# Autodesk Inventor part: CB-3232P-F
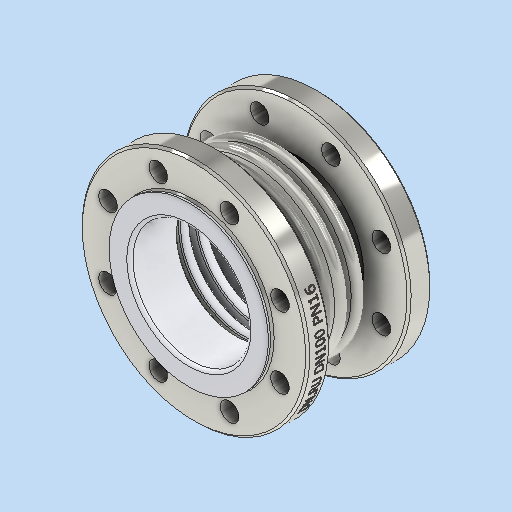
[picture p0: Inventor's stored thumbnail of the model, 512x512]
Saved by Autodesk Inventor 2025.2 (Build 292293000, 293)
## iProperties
Company: DN.RU
Created: 2026-04
Part Number: CB-3232P-F
Material: Типовые
Document SubType Name: Modeling
Designer: DN.RU
Density: 6.32462 g/cm^3
Appearance: По умолчанию
Description: D140-02141
Mass: 9000 g
Surface Area: 3707.62 cm^2
Volume: 1423.01 cm^3
Author: DN.RU
Title: Компенсатор сильфонный осевой DN.ru Ду100 Ру16
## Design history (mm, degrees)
sketch "Эскиз1"
  geometry: L1 (0, 0)-(0, -60); L2 (63, -60)-(63, 0); L3 (63, 0)-(0, 0); L4 (63, 0)-(63, 0); L5 (45, 0)-(81, 0); L6 (45, -5)-(81, -5); L7 (81, 5)-(45, 5); L8 (81, -3)-(45, -3); L9 (45, 3)-(81, 3); L10 (81, -11)-(45, -11); L11 (45, -13)-(81, -13); L12 (45, -16)-(81, -16); L13 (45, -21)-(81, -21); L14 (81, -19)-(45, -19); L15 (0, -60)-(63, -60); L16 (63, -60)-(57, -60); L17 (57, -60)-(57, -19); L18 (63, -13)-(61, -13); L19 (61, -13)-(61, -3); L20 (63, 3)-(62, 3); L21 (62, 3)-(61, 0); L22 (0, -60)-(0, -38); L23 (0, -38)-(110, -38); L24 (110, -38)-(110, -60); L25 (110, -60)-(0, -60); L26 (63, -38)-(63, -48); L27 (63, -48)-(66, -48); L28 (66, -48)-(66, -38); L29 (66, -38)-(63, -38); L30 (86, 0)-(63, 0); A1 r 5 centre (45, 0) between (45, 5) and (45, -5); A2 r 5 centre (81, 0) between (81, -5) and (81, 5); A3 r 3 centre (45, 0) between (45, 3) and (45, -3); A4 r 3 centre (81, 0) between (81, -3) and (81, 3); A5 r 3 centre (45, -16) between (45, -13) and (45, -19); A6 r 5 centre (45, -16) between (45, -11) and (45, -21); A7 r 3 centre (81, -16) between (81, -19) and (81, -13); A8 r 5 centre (81, -16) between (81, -21) and (81, -11); 18 further points
  constraints: 64 end point, 17 point on circle, 13 point on line, 8 centre point, 7 parallel, 4 perpendicular, 4 tangent, 3 midpoint, 2 vertical, 1 collinear, 1 horizontal, 25 other
  dimensions: "d0" = 60 distance of L1.start L1.end; "d3" = 0 distance of L2.end L4.end; "d4" = 18 distance of L4.end L5.end; "d5" = 10 diameter of A2; "d6" = 2 distance between parallel lines of L6 L8; "d9" = 16 distance of L4.end point (63, -16); "d18" = 2 distance of L18.start L18.end; "d19" = 1 distance of L20.start L20.end; "d27" = 57 distance between parallel lines of L1 L17; "d28" = 6 distance between parallel lines of L2 L17; "d29" = 22 distance of L1.end L22.end; "d30" = 110 distance of L22.end L23.end; "d31" = 10 distance of L26.start L26.end; "d32" = 3 distance of L27.end L26.end
revolve "Вращение1" sketch "Эскиз1" stored, may be unused: angle "d20" = 360 deg
sketch "Эскиз3" dims "d33" = 180
  geometry: L1 (0, 0)-(71.096, 29.449); L2 (0, 0)-(76.954, 0); C1 r 9 at (83.149, 34.442); C2 r 9 at (34.442, 83.149); C3 r 9 at (-34.442, 83.149); C4 r 9 at (-83.149, 34.442); C5 r 57 at (0, 0) reference; C6 r 77.5 at (0, 0); C7 r 110 at (0, 0) reference; C8 r 9 at (-83.149, -34.442); C9 r 9 at (-34.442, -83.149); C10 r 9 at (34.442, -83.149); C11 r 9 at (83.149, -34.442); 1 further point
  constraints: 9 centre point, 4 end point, 2 coincident, 1 equal length, 1 horizontal, 1 point on line, 20 other
  dimensions: "d34" = 22.5 deg angle of L2 L1; "d35" = 18 diameter of C1; "d38" = 360 deg dimension on point (0, 0) C1.centre (derived); "d40" = 155 diameter of C6
  node "Эскиз — круговой массив1" dims "d38" = 360 deg (derived)
extrude "Выдавливание1" cut sketch "Эскиз3" stored distance "d41" = 10; taper "d42" = 0 deg
extrude "Выдавливание2" join sketch "Эскиз3" distance "d43" = 3; taper "d44" = 0 deg
chamfer "Фаска2" distance "d45" = 3; stored, may be unused: second distance "d46" = 2, angle "d47" = 45 deg
chamfer "Фаска3" distance "d48" = 2; stored, may be unused: second distance "d49" = 2, angle "d50" = 45 deg
mirror "Зеркальное отражение2"
fillet "Сопряжение2" dims "d51" = 1
node "РабПлоскость2"
sketch "Эскиз4"
  geometry: L1 (-60.476, 3.302)-(81.492, 3.302); L2 (81.492, 3.302)-(81.492, -37.818); L3 (81.492, -37.818)-(-60.476, -37.818); L4 (-60.476, -37.818)-(-60.476, 3.302); 1 further point
  constraints: 2 other
feature "Рельеф2" sketch "Эскиз4" dims "d3" = 0, "d52" = 0.1, "d53" = 0
sketch "Эскиз5"
  geometry: C1 r 57 at (0, 0) reference; C2 r 77 at (0, 0); 1 further point
  constraints: 1 centre point
  dimensions: "d54" = 20 radial gap between concentric circles of C1 C2
extrude "Выдавливание3" join sketch "Эскиз5" distance "d55" = 2; taper "d56" = 0 deg
fillet "Сопряжение3" dims "d57" = 3
mirror "Зеркальное отражение3"
node "Твердое тело1"
node "Эскиз — прямоугольный массив1" dims "d9" = 16, "d12" = 10
